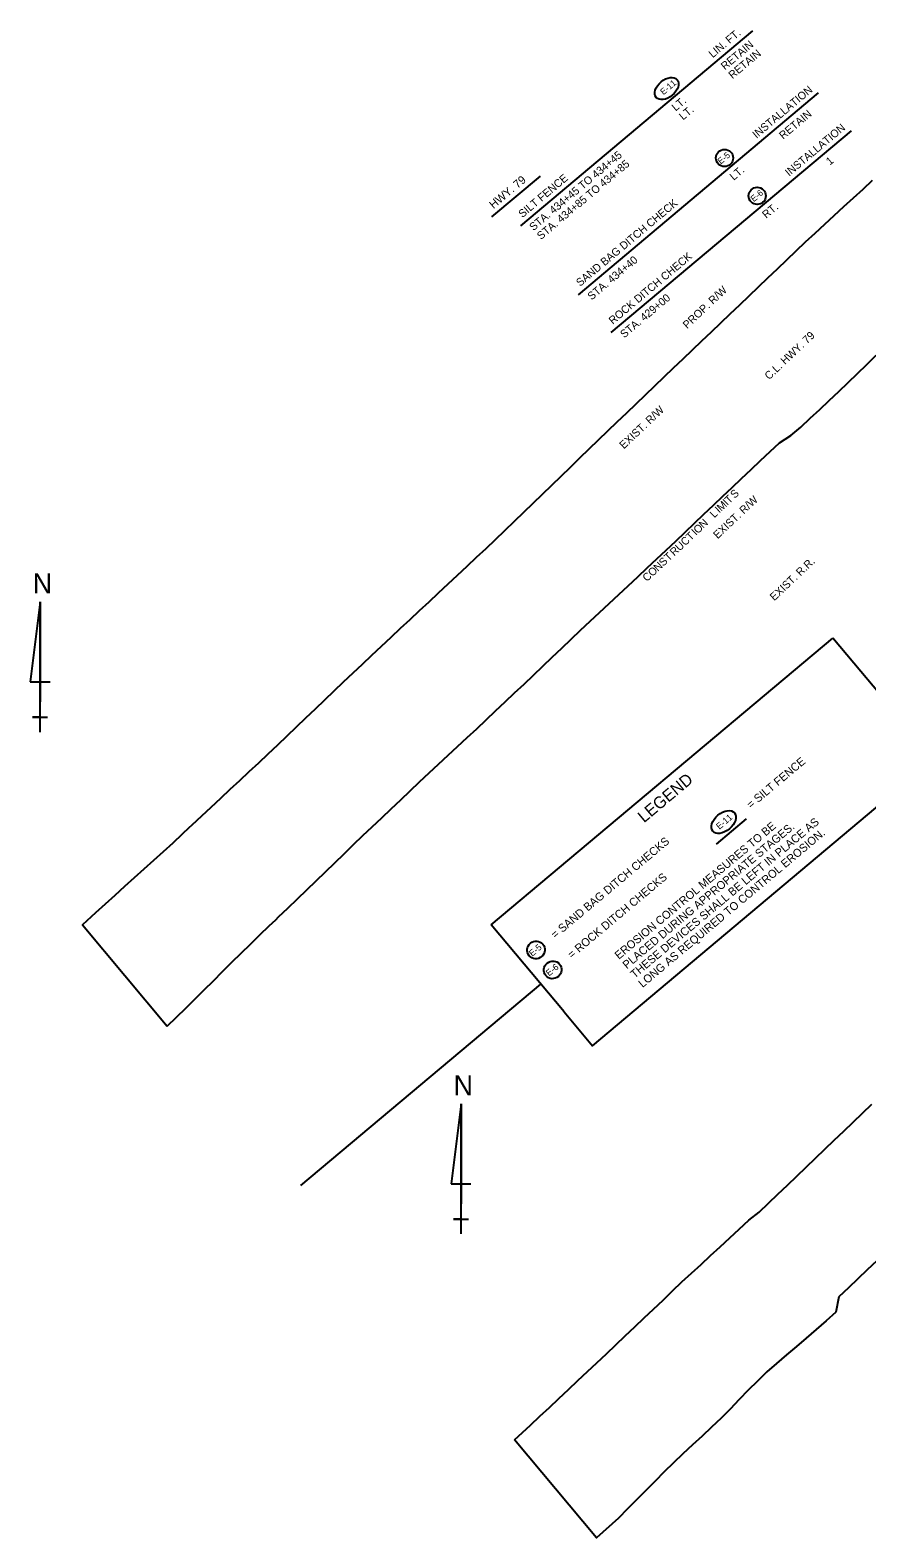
# Model space of a CAD drawing. Extents: x 1430270 to 1431940, y 1964631 to 1966264.
# Drawn here: x 1430270 to 1430913, y 1964631 to 1965788 of the extents above; entities that cross this region are included whole.
import ezdxf

# ---------------------------------------------------------------- set-up
doc = ezdxf.new("R2010")
doc.units = 0
for name, color, linetype in [('1', 7, 'Continuous'), ('44', 7, 'Continuous'), ('63', 7, 'Continuous'), ('Level 1', 7, 'Continuous'), ('Level 44', 7, 'Continuous'), ('R_Draft', 7, 'Continuous'), ('R_NO PLOT', 7, 'Continuous')]:
    doc.layers.add(name, color=color, linetype=linetype)

msp = doc.modelspace()

# ---------------------------------------------------------------- linework, layer by layer
at = {"layer": '1'}
for p, q in [((1430623.9, 1965101.3), (1430886.4, 1965321.6)), ((1430964.3, 1965228.8), (1430886.4, 1965321.6)), ((1430680, 1965034.6), (1430623.9, 1965101.3)), ((1430477.8, 1964901.3), (1430662.1, 1965055.9))]:
    msp.add_line(p, q, dxfattribs=at)
msp.add_lwpolyline([(1430680, 1965034.6), (1430701.8, 1965008.6), (1430964.3, 1965228.8)], dxfattribs=at)
for centre in [(1430803.3, 1965690.2), (1430828.4, 1965661.1)]:
    msp.add_circle(centre, 6.61, dxfattribs=at)
msp.add_ellipse((1430758.8, 1965743.5), major_axis=(8.06, 6.76), ratio=0.638788, dxfattribs=at)
at = {"layer": '44'}
for p, q in [((1430646.7, 1965638), (1430825, 1965787.7)), ((1430691, 1965585.2), (1430875.6, 1965740.1)), ((1430716.1, 1965556.1), (1430900.8, 1965711.1)), ((1430624.4, 1965644.9), (1430661.8, 1965676.3))]:
    msp.add_line(p, q, dxfattribs=at)
at = {"layer": '63'}
for p, q in [((1430277.4, 1965349.4), (1430269.7, 1965287.9)), ((1430277.4, 1965249.4), (1430277.4, 1965349.4)), ((1430277.4, 1965349.4), (1430277.4, 1965272.5)), ((1430269.7, 1965287.9), (1430285, 1965287.9)), ((1430277.4, 1965249.4), (1430277.4, 1965272.5)), ((1430277.4, 1965260.9), (1430271.6, 1965260.9)), ((1430271.6, 1965260.9), (1430283.1, 1965260.9)), ((1430277.4, 1965249.4), (1430277.4, 1965260.9)), ((1430600.8, 1964964), (1430593.1, 1964902.5)), ((1430600.8, 1964864), (1430600.8, 1964964)), ((1430600.8, 1964964), (1430600.8, 1964887.1)), ((1430593.1, 1964902.5), (1430608.4, 1964902.5)), ((1430600.8, 1964864), (1430600.8, 1964887.1)), ((1430600.8, 1964875.5), (1430595, 1964875.5)), ((1430595, 1964875.5), (1430606.5, 1964875.5)), ((1430600.8, 1964864), (1430600.8, 1964875.5))]:
    msp.add_line(p, q, dxfattribs=at)
at = {"layer": 'Level 1'}
for centre, major_axis, ratio in [((1430802.6, 1965180.3), (8.39, 7.04), 0.622952), ((1430658.4, 1965082.1), (-5.27, -4.42), 0.97521), ((1430671.3, 1965066.8), (-5.27, -4.42), 0.97521)]:
    msp.add_ellipse(centre, major_axis=major_axis, ratio=ratio, dxfattribs=at)
at = {"layer": 'Level 44'}
msp.add_lwpolyline([(1430797.1, 1965163.4), (1430820.2, 1965182.8)], dxfattribs=at)
at = {"layer": 'R_NO PLOT'}
for points in [[(1430916.8, 1965672.9), (1430909.5, 1965666.1), (1430902.1, 1965659.3), (1430894.7, 1965652.6), (1430887.4, 1965645.8), (1430880, 1965639), (1430872.6, 1965632.3), (1430865.3, 1965625.5), (1430858, 1965618.7), (1430850.8, 1965611.7), (1430843.6, 1965604.8), (1430836.4, 1965597.9), (1430829.1, 1965591), (1430821.9, 1965584), (1430814.7, 1965577.1), (1430807.4, 1965570.2), (1430800.2, 1965563.3), (1430793, 1965556.4), (1430785.7, 1965549.5), (1430778.5, 1965542.7), (1430771.2, 1965535.8), (1430763.9, 1965528.9), (1430756.7, 1965522), (1430749.5, 1965515.1), (1430742.3, 1965508.1), (1430735.1, 1965501.2), (1430727.9, 1965494.3), (1430720.6, 1965487.4), (1430713.4, 1965480.4), (1430706.3, 1965473.5), (1430699, 1965466.5), (1430691.8, 1965459.6), (1430684.7, 1965452.6), (1430677.4, 1965445.7), (1430670.2, 1965438.8), (1430663.1, 1965431.8), (1430655.9, 1965424.9), (1430648.7, 1965417.9), (1430641.5, 1965411), (1430634.3, 1965404), (1430627.1, 1965397.1), (1430619.8, 1965390.2), (1430612.5, 1965383.4), (1430605.2, 1965376.6), (1430597.9, 1965369.7), (1430590.6, 1965362.9), (1430583.3, 1965356.1), (1430576, 1965349.2), (1430568.7, 1965342.4), (1430561.4, 1965335.6), (1430554, 1965328.8), (1430546.8, 1965321.9), (1430539.4, 1965315.2), (1430532.1, 1965308.3), (1430524.8, 1965301.4), (1430517.6, 1965294.6), (1430510.3, 1965287.7), (1430503.1, 1965280.8), (1430495.9, 1965273.9), (1430488.7, 1965267), (1430481.4, 1965260), (1430474.2, 1965253.1), (1430466.9, 1965246.3), (1430459.7, 1965239.4), (1430452.4, 1965232.5), (1430445.1, 1965225.6), (1430437.8, 1965218.8), (1430430.5, 1965212), (1430423.2, 1965205.2), (1430415.9, 1965198.3), (1430408.6, 1965191.5), (1430401.3, 1965184.7), (1430394, 1965177.9), (1430391.7, 1965175.8), (1430386.6, 1965171), (1430379.3, 1965164.2), (1430371.9, 1965157.5), (1430364.5, 1965150.8), (1430357.1, 1965144), (1430349.6, 1965137.4), (1430342.2, 1965130.7), (1430334.8, 1965123.9), (1430327.4, 1965117.2), (1430320, 1965110.5), (1430309.9, 1965101.3), (1430375, 1965023.7)], [(1430375, 1965023.7), (1430389.2, 1965037.4), (1430396.3, 1965044.4), (1430403.4, 1965051.5), (1430410.5, 1965058.5), (1430417.6, 1965065.5), (1430424.7, 1965072.6), (1430431.9, 1965079.6), (1430439, 1965086.6), (1430446.2, 1965093.6), (1430453.4, 1965100.5), (1430458.4, 1965105.3), (1430460.5, 1965107.4), (1430467.8, 1965114.3), (1430475, 1965121.3), (1430482.2, 1965128.2), (1430489.4, 1965135.2), (1430496.6, 1965142.1), (1430503.8, 1965149), (1430511, 1965156), (1430518.1, 1965163), (1430525.3, 1965169.9), (1430532.6, 1965176.7), (1430539.9, 1965183.6), (1430547.2, 1965190.4), (1430554.5, 1965197.3), (1430561.7, 1965204.2), (1430569, 1965211.1), (1430576.2, 1965218), (1430583.5, 1965224.8), (1430590.9, 1965231.6), (1430598.2, 1965238.3), (1430605.6, 1965245.1), (1430612.9, 1965252), (1430620.1, 1965258.9), (1430627.4, 1965265.7), (1430634.7, 1965272.6), (1430641.9, 1965279.5), (1430649.2, 1965286.3), (1430656.5, 1965293.2), (1430663.7, 1965300.1), (1430670.9, 1965307), (1430678.2, 1965313.9), (1430685.4, 1965320.8), (1430692.7, 1965327.7), (1430700, 1965334.5), (1430707.3, 1965341.3), (1430714.7, 1965348.1), (1430722, 1965354.9), (1430729.3, 1965361.8), (1430736.6, 1965368.6), (1430743.9, 1965375.4), (1430751.2, 1965382.3), (1430758.5, 1965389.1), (1430765.8, 1965395.9), (1430773, 1965402.8), (1430780.2, 1965409.7), (1430787.5, 1965416.6), (1430794.7, 1965423.5), (1430802, 1965430.4), (1430809.2, 1965437.3), (1430816.4, 1965444.2), (1430823.7, 1965451.1), (1430830.9, 1965458), (1430838.3, 1965464.8), (1430845.6, 1965471.6), (1430854.3, 1965477), (1430861.8, 1965483.6), (1430869.2, 1965490.3), (1430876.6, 1965497), (1430883.7, 1965504.1), (1430891.1, 1965510.8), (1430898.3, 1965517.8), (1430905.5, 1965524.7), (1430912.7, 1965531.7), (1430919.8, 1965538.7)], [(1430822, 1964874.6), (1430829.8, 1964880.8), (1430837, 1964887.7), (1430844.3, 1964894.6), (1430851.6, 1964901.5), (1430858.8, 1964908.3), (1430866, 1964915.3), (1430873.2, 1964922.2), (1430880.4, 1964929.2), (1430887.6, 1964936.1), (1430894.9, 1964942.9), (1430902.1, 1964949.9), (1430909.4, 1964956.7), (1430916.6, 1964963.7)], [(1431014.7, 1964932.7), (1431007.4, 1964925.8), (1431000.2, 1964918.9), (1430992.9, 1964912), (1430985.7, 1964905.1), (1430978.4, 1964898.2), (1430971.2, 1964891.3), (1430963.9, 1964884.5), (1430956.7, 1964877.6), (1430949.4, 1964870.7), (1430942.2, 1964863.8), (1430934.9, 1964857), (1430927.6, 1964850.1), (1430920.3, 1964843.3), (1430913, 1964836.4), (1430905.8, 1964829.5), (1430898.5, 1964822.7), (1430891.2, 1964815.8)], [(1430641.8, 1964705.9), (1430654.1, 1964717.3), (1430661.4, 1964724.1), (1430668.7, 1964730.9), (1430676, 1964737.8), (1430683.3, 1964744.6), (1430690.6, 1964751.4), (1430697.9, 1964758.3), (1430705.2, 1964765.1), (1430712.5, 1964772), (1430719.8, 1964778.9), (1430727, 1964785.7), (1430734.3, 1964792.6), (1430741.5, 1964799.5), (1430748.7, 1964806.4), (1430756, 1964813.3), (1430763.2, 1964820.3), (1430770.4, 1964827.2), (1430777.8, 1964833.9), (1430785.2, 1964840.7), (1430792.5, 1964847.5), (1430799.9, 1964854.2), (1430807.3, 1964861), (1430814.6, 1964867.8), (1430822, 1964874.6)], [(1430891.2, 1964815.8), (1430888.7, 1964803.9), (1430881.3, 1964797.2), (1430873.8, 1964790.6), (1430866.1, 1964784.1), (1430858.5, 1964777.6), (1430850.9, 1964771.1), (1430843.3, 1964764.6), (1430835.7, 1964758.1), (1430828.5, 1964751.1), (1430821.5, 1964744), (1430814.6, 1964736.8), (1430807.6, 1964729.6), (1430800.6, 1964722.5), (1430793.3, 1964715.6), (1430786, 1964708.8), (1430778.7, 1964702), (1430771.3, 1964695.2), (1430764, 1964688.4), (1430756.9, 1964681.3), (1430749.9, 1964674.2), (1430742.8, 1964667.1), (1430735.7, 1964660), (1430728.8, 1964652.9), (1430721.7, 1964645.8), (1430704.9, 1964630.7), (1430641.8, 1964705.9)]]:
    msp.add_lwpolyline(points, dxfattribs=at)

# ---------------------------------------------------------------- texts
at = {"layer": '1'}
for s, p in [('E-11', (1430756.3, 1965738.3)), ('E-5 ', (1430800.4, 1965685.1)), ('E-6 ', (1430825.8, 1965656.2))]:
    msp.add_text(s, height=4.8, rotation=40, dxfattribs=at).set_placement(p)
at = {"layer": '44'}
for s, height, p in [('LIN. FT.', 6, (1430794.2, 1965766.7)), ('RETAIN', 6, (1430803.6, 1965757.4)), ('RETAIN', 6, (1430809.4, 1965750.6)), ('INSTALLATION', 6, (1430827.8, 1965704.9)), ('LT.', 6, (1430765.7, 1965725.8)), ('LT.', 6, (1430771.4, 1965718.9)), ('RETAIN', 6, (1430848.3, 1965704.2)), ('INSTALLATION', 6, (1430852.9, 1965675.8)), ('STA. 434+45 TO 434+45', 6, (1430656.4, 1965633.9)), ('STA. 434+85 TO 434+85', 6, (1430662.2, 1965627.1)), ('LT.', 6, (1430810.3, 1965672.6)), ('1', 6, (1430884.3, 1965684.3)), ('HWY. 79', 6.25, (1430625.7, 1965650.9)), ('SILT FENCE      ', 6, (1430648, 1965644)), ('SAND BAG DITCH CHECK', 6, (1430692.3, 1965591.2)), ('RT.', 6, (1430835.3, 1965643.4)), ('STA. 434+40', 6, (1430701.1, 1965580.7)), ('ROCK DITCH CHECK', 6, (1430717.4, 1965562.1)), ('STA. 429+00', 6, (1430726.2, 1965551.6))]:
    msp.add_text(s, height=height, rotation=40, dxfattribs=at).set_placement(p)
at = {"layer": '63'}
for p in [(1430271.7, 1965355.8), (1430595.1, 1964970.4)]:
    msp.add_text('N', height=15.4, rotation=360, dxfattribs=at).set_placement(p)
at = {"layer": 'Level 1'}
for s, height, p in [('= SILT FENCE', 6.25, (1430823.5, 1965190.2)), ('E-11 ', 4.88, (1430799.3, 1965174.3)), ('EROSION CONTROL MEASURES TO BE', 6.25, (1430722.1, 1965074.5)), ('PLACED DURING APPROPRIATE STAGES. ', 6.25, (1430728.2, 1965067.2)), ('THESE DEVICES SHALL BE LEFT IN PLACE AS ', 6.25, (1430734.2, 1965060)), ('LONG AS REQUIRED TO CONTROL EROSION.', 6.25, (1430740.3, 1965052.8)), ('= SAND BAG DITCH CHECKS', 6.25, (1430673.1, 1965090.4)), ('= ROCK DITCH CHECKS', 6.25, (1430685.9, 1965075.1)), ('E-5 ', 4.88, (1430655.5, 1965076.8)), ('E-6 ', 4.88, (1430668.5, 1965061.7))]:
    msp.add_text(s, height=height, rotation=40, dxfattribs=at).set_placement(p)
at = {"layer": 'Level 44'}
msp.add_text('LEGEND', height=9.14, rotation=40, dxfattribs=at).set_placement((1430741.4, 1965179.3))
at = {"layer": 'R_Draft'}
for s, rotation, p in [('PROP. R/W', 43.366, (1430774.6, 1965558.7)), ('C.L. HWY. 79', 43.4244, (1430837.5, 1965519.5)), ('EXIST. R/W', 43.366, (1430725.9, 1965466.4)), ('EXIST. R/W', 43.366, (1430798, 1965397.4)), ('I', 43.6311, (1430805.4, 1965423)), ('T', 43.6311, (1430806.9, 1965424.3)), ('S', 43.6311, (1430811.1, 1965428.4)), ('L', 43.6093, (1430795.4, 1965413.4)), ('I', 43.5979, (1430799.3, 1965417.2)), ('M', 43.5979, (1430800.8, 1965418.5)), ('I', 43.616, (1430781.3, 1965400)), ('O', 43.616, (1430782.8, 1965401.3)), ('N', 43.6682, (1430787, 1965405.4)), ('U', 43.0886, (1430768.7, 1965388)), ('C', 43.6325, (1430773, 1965392)), ('T', 43.616, (1430777.1, 1965395.9)), ('S', 43.1198, (1430756.2, 1965376.3)), ('T', 43.1198, (1430760.3, 1965380.2)), ('R', 43.0886, (1430764.6, 1965384.2)), ('C', 43.1302, (1430743.6, 1965364.5)), ('O', 43.1401, (1430747.8, 1965368.4)), ('N', 43.1401, (1430752.1, 1965372.4)), ('EXIST. R.R.', 43.3919, (1430841.5, 1965349.8))]:
    msp.add_text(s, height=6, rotation=rotation, dxfattribs=at).set_placement(p)

doc.saveas('drawing.dxf')
